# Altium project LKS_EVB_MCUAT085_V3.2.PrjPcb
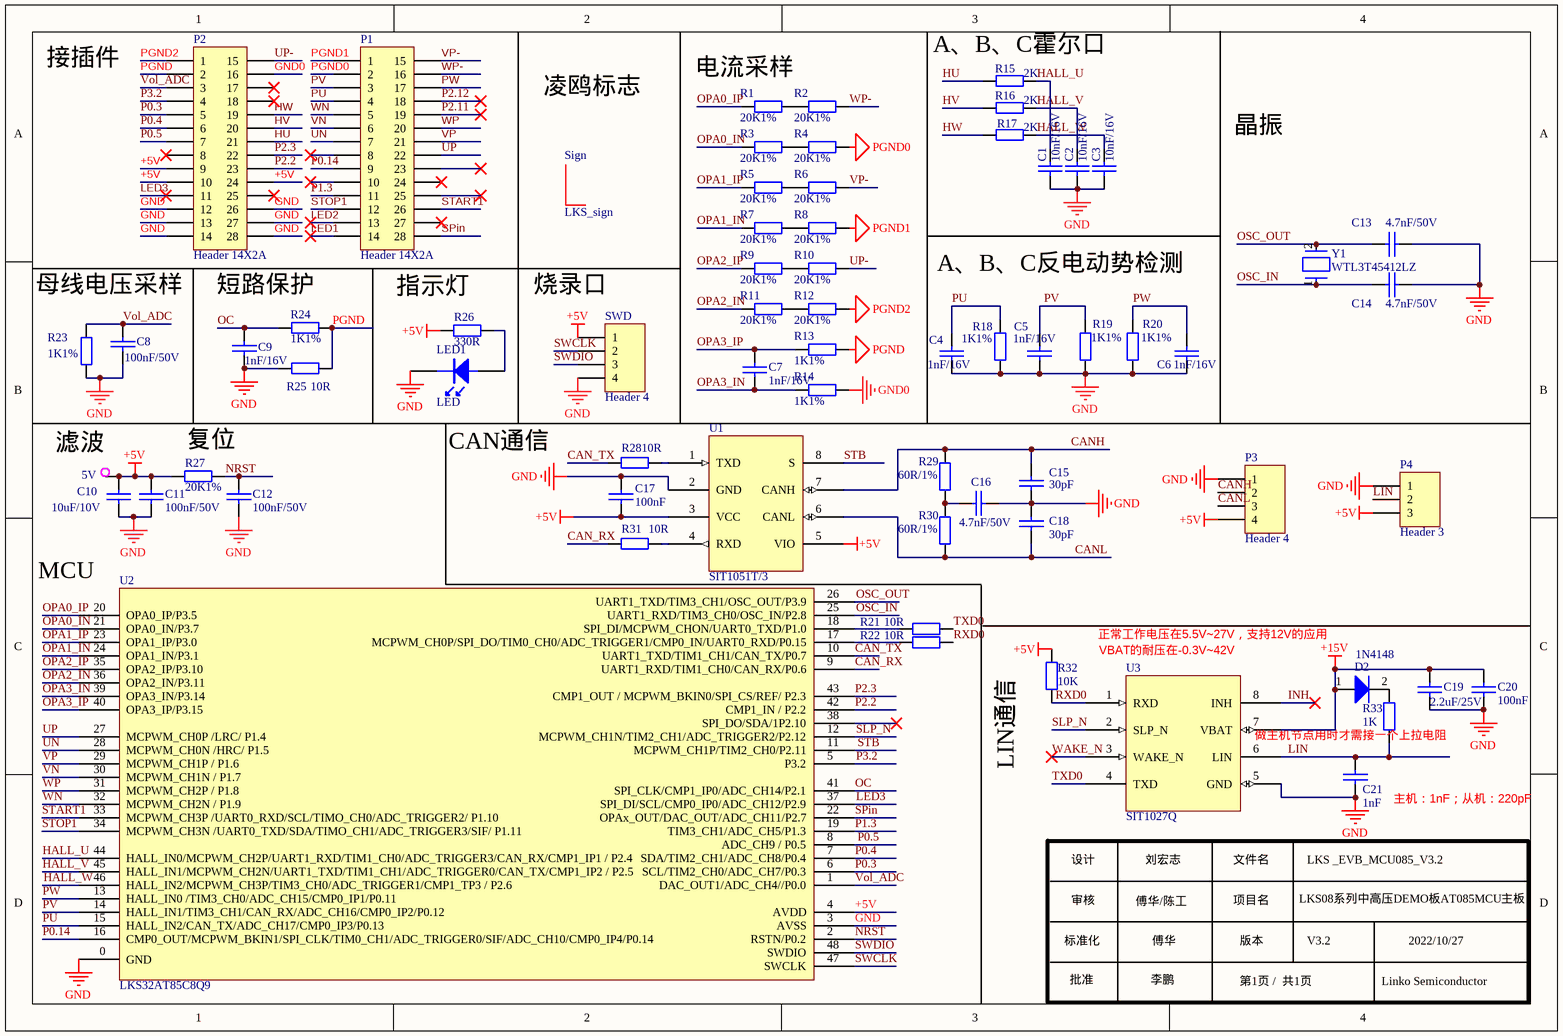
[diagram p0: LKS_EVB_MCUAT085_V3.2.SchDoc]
1 sheet, 67 parts. Net scope: global (net labels, ports and power ports of the same name join across sheets).
Board file: LKS_EVB_MCUAT085_V3.2.PcbDoc

## Sheet LKS_EVB_MCUAT085_V3.2.SchDoc
size A4; SheetNumber: 1; SheetTotal: 1

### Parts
5V  TestP  [TP-40]  (value not drawn)
C1  10nF/16V  [0603C]
C2  10nF/16V  [0603C]
C3  10nF/16V  [0603C]
C4  1nF/16V  [0603C]
C5  1nF/16V  [0603C]
C6  1nF/16V  [0603C]
C7  1nF/16V  [0603C]
C8  100nF/50V  [0603C]
C9  1nF/16V  [0603C]
C10  10uF/10V  [0603C]
C11  100nF/50V  [0603C]
C12  100nF/50V  [0603C]
C13  4.7nF/50V  [0603C _1]
C14  4.7nF/50V  [0603C _1]
C15  30pF  [0603C _1]
C16  4.7nF/50V  [0603C _1]
C17  100nF  [0603C _1]
C18  30pF  [0603C _1]
C19  2.2uF/25V  [0603C _1]
C20  100nF  [0603C _1]
C21  1nF  [0805C]
D2  1N4148  [SOD123]
LED1  LED  [LED 0603R]
P1  Header 14X2A  [HDR2X14_CEN]
P2  Header 14X2A  [HDR2X14_CEN]
P3  Header 4  [HDR1X4]
P4  Header 3  [HDR1X3]
R1  20K1%  [0603R]
R2  20K1%  [0603R]
R3  20K1%  [0603R]
R4  20K1%  [0603R]
R5  20K1%  [0603R]
R6  20K1%  [0603R]
R7  20K1%  [0603R]
R8  20K1%  [0603R]
R9  20K1%  [0603R]
R10  20K1%  [0603R]
R11  20K1%  [0603R]
R12  20K1%  [0603R]
R13  1K1%  [0603R]
R14  1K1%  [0603R]
R15  2K  [0603R]
R16  2K  [0603R]
R17  2K  [0603R]
R18  1K1%  [0603R]
R19  1K1%  [0603R]
R20  1K1%  [0603R]
R21  10R  [0603R]
R22  10R  [0603R]
R23  1K1%  [0603R]
R24  1K1%  [0603R]
R25  10R  [0603R]
R26  330R  [0603R]
R27  20K1%  [0603R]
R28  10R  [0603R_1]
R29  60R/1%  [0603R_1]
R30  60R/1%  [0603R_1]
R31  10R  [0603R_1]
R32  10K  [0603R_1]
R33  1K  [0603R_1]
Sign  LKS_sign  [PCBComponent_1]
SWD  Header 4  [HDR1X4]
U1  SIT1051T/3  [SOP-8N]
U2  LKS32AT85C8Q9  [LKS085-QFN48]
U3  SIT1027Q  [SOP-8N]
Y1  WTL3T45412LZ  [DT-38]

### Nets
+5V: 5V.1 C10.2 C11.2 C17.2 P2.9 P2.10 P2.24 P3.4 P4.3 R26.1 R27.2 R32.1 SWD.1 U1.3(VCC) U1.5(VIO) U2.4(AVDD)
+15V: C19.1 C20.1 D2.1(A) U3.7(VBAT)
GND: C1.2 C2.2 C3.2 C4.2 C5.2 C6.2 C8.1 C9.1 C10.1 C11.1 C12.2 C13.2 C14.2 C15.2 C16.2 C17.1 C18.1 C19.2 C20.2 C21.2 LED1.2(K) P2.12 P2.13 P2.14 P2.26 P2.27 P2.28 P3.1 P4.1 R18.2 R19.2 R20.2 R23.1 R25.2 SWD.4 U1.2(GND) U2.0(GND) U2.3(AVSS) U3.5(GND)
GND0: P2.16 R14.1
PGND: P2.2 R13.1 R24.2 R25.1
PGND0: P1.2 R4.1
PGND1: P1.1 R8.1
PGND2: P2.1 R12.1
CAN_RX: R31.1 U2.9(UART1_RXD/TIM1_CH0/CAN_RX/P0.6)
CAN_TX: R28.1 U2.10(UART1_TXD/TIM1_CH1/CAN_TX/P0.7)
CANH: C15.1 P3.2 R29.1 U1.7(CANH)
CANL: C18.2 P3.3 R30.2 U1.6(CANL)
HALL_U: C1.1 R15.2 U2.44(HALL_IN0/MCPWM_CH2P/UART1_RXD/TIM1_CH0/ADC_TRIGGER3/CAN_RX/CMP1_IP1_/_P2.4)
HALL_V: C2.1 R16.2 U2.45(HALL_IN1/MCPWM_CH2N/UART1_TXD/TIM1_CH1/ADC_TRIGGER0/CAN_TX/CMP1_IP2_/_P2.5)
HALL_W: C3.1 R17.2 U2.46(HALL_IN2/MCPWM_CH3P/TIM3_CH0/ADC_TRIGGER1/CMP1_TP3_/_P2.6)
HU: P2.21 R15.1
HV: P2.20 R16.1
HW: P2.19 R17.1
INH: U3.8(INH)
LED1: P1.14
LED2: P1.13
LED3: P2.11 U2.37(SPI_DI/SCL/CMP0_IP0/ADC_CH12/P2.9)
LIN: C21.1 P4.2 R33.2 U3.6(LIN)
NRST: C12.1 R27.1 U2.2(RSTN/P0.2)
OC: C9.2 R24.1 U2.41(SPI_CLK/CMP1_IP0/ADC_CH14/P2.1)
OPA0_IN: R3.2 U2.21(OPA0_IN/P3.7)
OPA0_IP: R1.2 U2.20(OPA0_IP/P3.5)
OPA1_IN: R7.2 U2.24(OPA1_IN/P3.1)
OPA1_IP: R5.2 U2.23(OPA1_IP/P3.0)
OPA2_IN: R11.2 U2.36(OPA2_IN/P3.11)
OPA2_IP: R9.2 U2.35(OPA2_IP/P3.10)
OPA3_IN: C7.2 R14.2 U2.39(OPA3_IN/P3.14)
OPA3_IP: C7.1 R13.2 U2.40(OPA3_IP/P3.15)
OSC_IN: C14.1 U2.25(UART1_RXD/TIM3_CH0/OSC_IN/P2.8) Y1.1
OSC_OUT: C13.1 U2.26(UART1_TXD/TIM3_CH1/OSC_OUT/P3.9) Y1.2
P0.3: P2.5 U2.6(SCL/TIM2_CH0/ADC_CH7/P0.3)
P0.4: P2.6 U2.7(SDA/TIM2_CH1/ADC_CH8/P0.4)
P0.5: P2.7 U2.8(ADC_CH9_/_P0.5)
P0.14: P1.9 U2.16(CMP0_OUT/MCPWM_BKIN1/SPI_CLK/TIM0_CH1/ADC_TRIGGER0/SIF/ADC_CH10/CMP0_IP4/P0.14)
P1.3: P1.11 U2.19(TIM3_CH1/ADC_CH5/P1.3)
P2.2: P2.23 U2.42(CMP1_IN_/_P2.2)
P2.3: P2.22 U2.43(CMP1_OUT_/_MCPWM_BKIN0/SPI_CS/REF/_P2.3)
P2.11: P1.19
P2.12: P1.18
P3.2: P2.4 U2.5(P3.2)
PU: C4.1 P1.4 R18.1 U2.15(HALL_IN2/CAN_TX/ADC_CH17/CMP0_IP3/P0.13)
PV: C5.1 P1.3 R19.1 U2.14(HALL_IN1/TIM3_CH1/CAN_RX/ADC_CH16/CMP0_IP2/P0.12)
PW: C6.1 P1.17 R20.1 U2.13(HALL_IN0_/TIM3_CH0/ADC_CH15/CMP0_IP1/P0.11)
RXD0: R22.2 R32.2 U3.1(RXD)
SLP_N: U2.12(MCPWM_CH1N/TIM2_CH1/ADC_TRIGGER2/P2.12) U3.2(SLP_N)
SPin: P1.28 U2.22(OPAx_OUT/DAC_OUT/ADC_CH11/P2.7)
START1: P1.26 U2.33(MCPWM_CH3P_/UART0_RXD/SCL/TIMO_CH0/ADC_TRIGGER2/_P1.10)
STB: U1.8(S) U2.11(MCPWM_CH1P/TIM2_CH0/P2.11)
STOP1: P1.12 U2.34(MCPWM_CH3N_/UART0_TXD/SDA/TIMO_CH1/ADC_TRIGGER3/SIF/_P1.11)
SWCLK: SWD.2 U2.47(SWCLK)
SWDIO: SWD.3 U2.48(SWDIO)
TXD0: R21.1 U3.4(TXD)
UN: P1.7 U2.28(MCPWM_CH0N_/HRC/_P1.5)
UP: P1.22 U2.27(MCPWM_CH0P_/LRC/_P1.4)
UP-: P2.15 R10.1
VN: P1.6 U2.30(MCPWM_CH1N_/_P1.7)
Vol_ADC: C8.2 P2.3 R23.2 U2.1(DAC_OUT1/ADC_CH4//P0.0)
VP: P1.21 U2.29(MCPWM_CH1P_/_P1.6)
VP-: P1.15 R6.1
WAKE_N: U3.3(WAKE_N)
WN: P1.5 U2.32(MCPWM_CH2N_/_P1.9)
WP: P1.20 U2.31(MCPWM_CH2P_/_P1.8)
WP-: P1.16 R2.1
NetC16_1: C16.1 R29.2 R30.1
NetD2_2: D2.2(K) R33.1
NetLED1_1: LED1.1(A) R26.2
NetR1_1: R1.1 R2.2
NetR3_1: R3.1 R4.2
NetR5_1: R5.1 R6.2
NetR7_1: R7.1 R8.2
NetR9_1: R9.1 R10.2
NetR11_1: R11.1 R12.2
NetR21_2: R21.2 U2.18(SPI_DI/MCPWM_CHON/UART0_TXD/P1.0)
NetR22_1: R22.1 U2.17(MCPWM_CH0P/SPI_DO/TIM0_CH0/ADC_TRIGGER1/CMP0_IN/UART0_RXD/P0.15)
NetR28_2: R28.2 U1.1(TXD)
NetR31_2: R31.2 U1.4(RXD)

Not connected (* = marked no-connect by the designer): P1 8* 10* 23* 24* 25* 27*; P2 8* 17* 18* 25*; U2 38(SPI_DO/SDA/1P2.10)*

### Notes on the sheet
- 接插件
- 凌鸥标志
- (near R1) 电流采样
- (near R15) A、B、C霍尔口
- 晶振
- 母线电压采样
- 短路保护
- 指示灯
- 烧录口
- A、B、C反电动势检测
- (near R27) 复位
- CAN通信
- 滤波
- MCU
- 正常工作电压在5.5V|7V，支持12V的应用
- VBAT的耐压在-0.3V~42V
- (near R32) LIN通信
- (near U3) 做主机节点用时才需接一个上拉电阻
- (near C21) 主机：1nF；从机：220pF
- 设计
- 审核
- 傅华/陈工
- 刘宏志
- 文件名
- 项目名
- LKS08系列中高压DEMO板AT085MCU主板
- LKS _EVB_MCU085_V3.2
- 标准化
- 批准
- 李鹏
- 傅华
- 版本
- 第1页 /  共1页
- V3.2
- Linko Semiconductor
- 2022/10/27

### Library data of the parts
5V = TestP: 测试点
C1-C6 = CAP: Capacitor
C7-C12 = C: Capacitor
C13-C21 = Capacitor: Capacitor --贴片电容
D2 = Diode: Default Diode
LED1 = LED: 发光二极管
P1 P2 = Header 14X2A: Header, 14-Pin, Dual row
P3 SWD = Header 4: Header, 4-Pin
P4 = Header 3: Header, 3-Pin
R1-R25 R27-R33 = Res: Resistor; Value: K
R26 = Res: Resistor; Value: 330
Sign = LKS_sign: 凌鸥公司图标/丝印
U1 = SIT1051T/3: SIT芯力特CAN芯片  sop-8
U2 = LKS085: 车规芯片
U3 = SIT1021T: SIT芯力特LIN芯片  SOP-8
Y1 = Crystal: CRYSTAL 圆柱体晶振 频率：4MHz 频率公差：±20ppm 频率稳定度：±20ppm 负载电容：20pF 等效串联电阻(ESR)：150Ω 工作温度：-20℃~+70℃; Manufacturer: Abracon; Manufacturer Part Number: AB26TRB-32.768KHZ-T; Load Capacitance: 12.5pF; Operating Frequency: 32.768 kHz; Series Resistance: 50kR; Frequency Tolerance: 20ppm; Frequency Stability: -0.034ppm; Frequency: 32.768kHz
